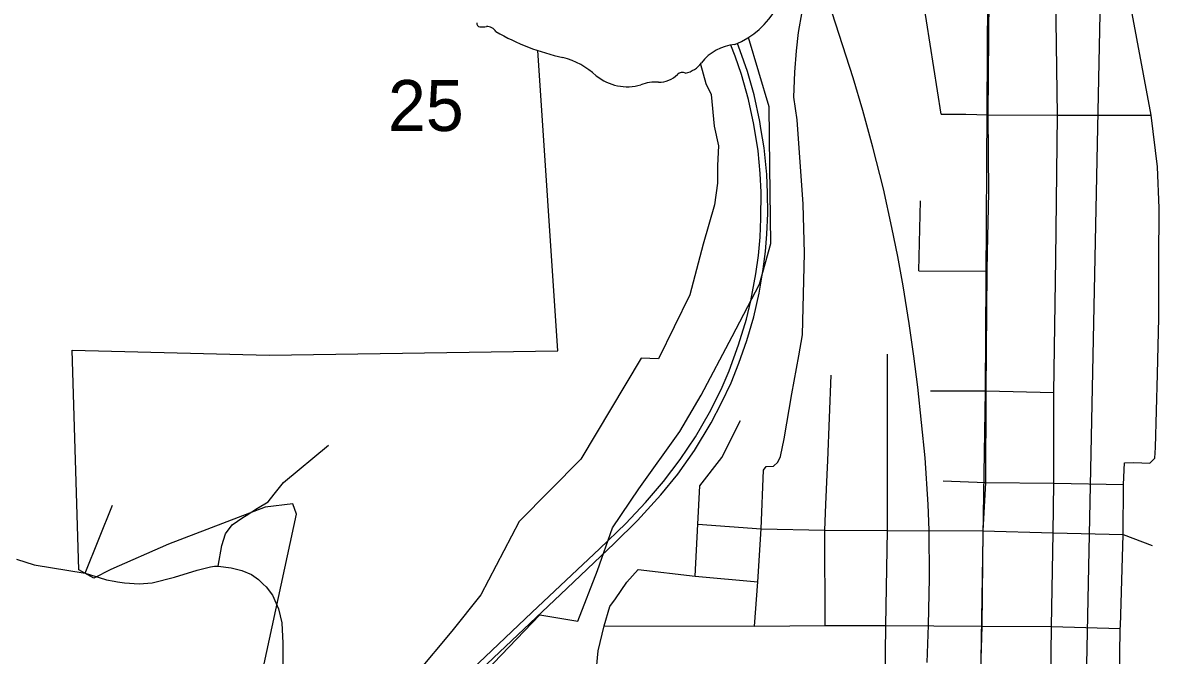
# Model space of a CAD drawing. Extents: x 0 to 34, y 0 to 22.
# Drawn here: x 7.567 to 8.5, y 19.139 to 19.658 of the extents above; entities that cross this region are included whole.
import ezdxf

# ---------------------------------------------------------------- set-up
doc = ezdxf.new("R2010")
doc.units = 0
for name, color, linetype in [('GM_X_City_Street', 7, 'Continuous'), ('GM_X_Corporation', 7, 'Continuous'), ('GM_X_County_Road', 7, 'Continuous'), ('GM_X_Rail_Line', 7, 'Continuous'), ('GM_X_Section', 7, 'Continuous'), ('GM_X_Section_Text', 7, 'Continuous'), ('GM_X_State_Route', 7, 'Continuous'), ('GM_X_State_Shield', 7, 'Continuous')]:
    doc.layers.add(name, color=color, linetype=linetype)

msp = doc.modelspace()

# ---------------------------------------------------------------- linework, layer by layer
at = {"layer": 'GM_X_City_Street'}
for p, q in [((8.32123, 19.58328), (8.30533, 19.68449)), ((8.49377, 19.58232), (8.47461, 19.68388)), ((8.20392, 19.65034), (8.20705, 19.66728)), ((8.20236, 19.63522), (8.20392, 19.65034)), ((8.20106, 19.61775), (8.20236, 19.63522)), ((8.20001, 19.59716), (8.20106, 19.61775)), ((8.20288, 19.57865), (8.20001, 19.59716)), ((8.20783, 19.50931), (8.20288, 19.57865)), ((8.32123, 19.58328), (8.34153, 19.58328)), ((8.34153, 19.58328), (8.35941, 19.5828)), ((8.35941, 19.5828), (8.41668, 19.58232)), ((8.41668, 19.58232), (8.49377, 19.58232)), ((8.49884, 19.54003), (8.49377, 19.58232)), ((8.50029, 19.50596), (8.49884, 19.54003)), ((8.30272, 19.45456), (8.30403, 19.51217)), ((8.20888, 19.46916), (8.20783, 19.50931)), ((8.50005, 19.46198), (8.50029, 19.50596)), ((8.20835, 19.44648), (8.20888, 19.46916)), ((8.4998, 19.41607), (8.50005, 19.46198)), ((8.30272, 19.45456), (8.35869, 19.45425)), ((8.20731, 19.4019), (8.20835, 19.44648)), ((8.49884, 19.36968), (8.4998, 19.41607)), ((8.20418, 19.3847), (8.20731, 19.4019)), ((8.19845, 19.35341), (8.20418, 19.3847)), ((8.27718, 19.26269), (8.27718, 19.386)), ((8.22791, 19.29867), (8.23077, 19.36879)), ((8.49715, 19.3095), (8.49884, 19.36968)), ((8.19219, 19.31666), (8.19845, 19.35341)), ((8.31229, 19.3559), (8.33911, 19.3559)), ((8.33911, 19.3559), (8.34609, 19.3559)), ((8.34609, 19.3559), (8.35772, 19.3559)), ((8.35772, 19.3559), (8.41378, 19.35469)), ((8.14084, 19.30127), (8.15624, 19.33163)), ((8.18906, 19.30206), (8.19219, 19.31666)), ((8.49666, 19.3008), (8.49715, 19.3095)), ((8.12289, 19.27788), (8.14084, 19.30127)), ((8.18333, 19.29424), (8.18698, 19.29736)), ((8.18698, 19.29736), (8.18906, 19.30206)), ((8.22739, 19.2872), (8.22791, 19.29867)), ((8.47177, 19.29694), (8.4795, 19.29718)), ((8.4795, 19.29718), (8.49255, 19.2967)), ((8.49255, 19.2967), (8.49666, 19.3008)), ((8.17316, 19.24262), (8.17523, 19.29086)), ((8.17523, 19.29086), (8.17733, 19.29398)), ((8.17733, 19.29398), (8.18333, 19.29424)), ((8.47092, 19.27913), (8.47177, 19.29694)), ((8.2264, 19.26263), (8.22739, 19.2872)), ((8.3228, 19.28198), (8.35748, 19.28075)), ((8.35748, 19.28075), (8.41378, 19.28003)), ((8.41378, 19.28003), (8.47092, 19.27913)), ((8.47061, 19.23793), (8.47092, 19.27913)), ((8.12126, 19.24647), (8.12289, 19.27788)), ((7.61789, 19.20638), (7.64044, 19.26196)), ((8.22556, 19.24158), (8.2264, 19.26263)), ((8.27718, 19.24132), (8.27718, 19.26269)), ((8.11914, 19.20384), (8.12126, 19.24647)), ((8.12126, 19.24647), (8.17316, 19.24262)), ((8.17055, 19.19908), (8.17316, 19.24262)), ((8.17316, 19.24262), (8.22556, 19.24158)), ((8.22556, 19.24158), (8.27718, 19.24132)), ((8.22582, 19.16337), (8.22556, 19.24158)), ((8.27561, 19.16337), (8.27718, 19.24132)), ((8.27718, 19.24132), (8.35538, 19.24106)), ((8.35538, 19.24106), (8.413, 19.23949)), ((8.413, 19.23949), (8.47061, 19.23793)), ((8.46832, 19.16272), (8.47061, 19.23793)), ((8.47061, 19.23793), (8.49433, 19.22906)), ((8.06289, 19.19882), (8.07228, 19.20925)), ((8.07228, 19.20925), (8.11914, 19.20384)), ((8.11914, 19.20384), (8.17055, 19.19908)), ((8.05351, 19.18527), (8.06289, 19.19882)), ((8.16769, 19.16285), (8.17055, 19.19908)), ((8.04907, 19.17875), (8.05351, 19.18527)), ((8.04438, 19.16311), (8.04907, 19.17875)), ((8.03943, 19.14251), (8.04438, 19.16311)), ((8.04438, 19.16311), (8.16769, 19.16285)), ((8.16769, 19.16285), (8.22582, 19.16337)), ((8.22582, 19.16337), (8.27561, 19.16337)), ((8.27513, 19.10024), (8.27561, 19.16337)), ((8.27561, 19.16337), (8.3546, 19.16285)), ((8.3546, 19.16285), (8.41169, 19.16233)), ((8.41169, 19.16233), (8.46826, 19.16076)), ((8.46748, 19.10967), (8.46826, 19.16076)), ((8.46826, 19.16076), (8.46832, 19.16272)), ((8.03812, 19.12792), (8.03943, 19.14251))]:
    msp.add_line(p, q, dxfattribs=at)
at = {"layer": 'GM_X_Corporation'}
for p, q in [((8.17973, 19.58928), (8.16281, 19.64611)), ((8.00622, 19.38873), (7.98974, 19.63551)), ((8.12332, 19.62431), (8.12779, 19.60835)), ((8.12779, 19.60835), (8.13227, 19.59941)), ((8.13227, 19.59941), (8.13477, 19.57335)), ((8.18042, 19.54022), (8.17973, 19.58928)), ((8.13477, 19.57335), (8.13818, 19.55712)), ((8.13818, 19.55712), (8.13737, 19.54107)), ((8.13737, 19.54107), (8.13736, 19.52664)), ((8.18121, 19.47708), (8.18042, 19.54022)), ((8.13736, 19.52664), (8.13503, 19.50885)), ((8.13503, 19.50885), (8.12573, 19.47639)), ((8.12573, 19.47639), (8.1146, 19.43478)), ((8.17183, 19.44372), (8.18121, 19.47708)), ((8.14956, 19.40074), (8.17183, 19.44372)), ((8.1146, 19.43478), (8.08899, 19.38237)), ((8.12395, 19.35231), (8.14956, 19.40074)), ((7.61267, 19.20906), (7.60727, 19.38935)), ((7.60727, 19.38935), (7.76922, 19.38533)), ((7.76922, 19.38533), (8.00622, 19.38873)), ((8.07464, 19.38285), (8.02502, 19.29976)), ((8.08899, 19.38237), (8.07464, 19.38285)), ((8.10642, 19.3227), (8.12395, 19.35231)), ((8.07274, 19.27562), (8.10642, 19.3227)), ((8.02502, 19.29976), (7.97441, 19.24867)), ((8.05118, 19.24334), (8.07274, 19.27562)), ((7.76576, 19.26035), (7.68632, 19.23008)), ((7.78871, 19.26305), (7.76576, 19.26035)), ((7.7916, 19.25476), (7.78871, 19.26305)), ((7.75651, 19.09318), (7.7916, 19.25476)), ((7.97441, 19.24867), (7.94289, 19.18858)), ((8.03891, 19.20857), (8.05118, 19.24334)), ((7.68632, 19.23008), (7.63909, 19.20926)), ((7.6252, 19.20212), (7.61267, 19.20906)), ((7.63909, 19.20926), (7.6252, 19.20212)), ((8.0228, 19.16687), (8.03891, 19.20857)), ((7.94289, 19.18858), (7.9193, 19.15858)), ((7.94699, 19.12564), (7.99145, 19.17211)), ((7.99145, 19.17211), (8.0228, 19.16687)), ((7.9193, 19.15858), (7.89001, 19.12359))]:
    msp.add_line(p, q, dxfattribs=at)
at = {"layer": 'GM_X_County_Road'}
for p, q in [((8.36027, 19.68458), (8.35941, 19.5828)), ((8.41668, 19.58232), (8.41513, 19.68462)), ((8.35941, 19.5828), (8.35989, 19.51877)), ((8.41523, 19.4644), (8.41668, 19.58232)), ((8.35989, 19.51877), (8.35898, 19.46989)), ((8.35898, 19.46989), (8.35869, 19.45425)), ((8.41378, 19.35469), (8.41523, 19.4644)), ((8.35869, 19.45425), (8.35772, 19.3559)), ((8.35772, 19.3559), (8.35771, 19.35297)), ((8.41378, 19.28003), (8.41378, 19.35469)), ((8.35771, 19.35297), (8.35748, 19.28075)), ((7.78083, 19.28066), (7.81794, 19.31131)), ((7.77337, 19.27109), (7.78083, 19.28066)), ((8.35748, 19.28075), (8.35538, 19.24106)), ((8.413, 19.23949), (8.41378, 19.28003)), ((7.76839, 19.26471), (7.77337, 19.27109)), ((7.75964, 19.25966), (7.76839, 19.26471)), ((7.73864, 19.24585), (7.74758, 19.25208)), ((7.74758, 19.25208), (7.75017, 19.2537)), ((7.75017, 19.2537), (7.75964, 19.25966)), ((7.73319, 19.23847), (7.73864, 19.24585)), ((7.73028, 19.22894), (7.73319, 19.23847)), ((8.35538, 19.24106), (8.3546, 19.16285)), ((8.41169, 19.16233), (8.413, 19.23949)), ((7.72736, 19.21202), (7.73028, 19.22894)), ((7.5615, 19.21785), (7.57609, 19.21299)), ((7.57609, 19.21299), (7.61789, 19.20638)), ((7.61789, 19.20638), (7.63459, 19.20099)), ((7.69149, 19.20308), (7.71006, 19.20872)), ((7.71006, 19.20872), (7.72094, 19.21144)), ((7.72094, 19.21144), (7.72425, 19.21202)), ((7.72425, 19.21202), (7.72736, 19.21202)), ((7.72736, 19.21202), (7.73786, 19.21066)), ((7.73786, 19.21066), (7.74661, 19.20852)), ((7.74661, 19.20852), (7.75458, 19.20502)), ((7.75458, 19.20502), (7.76042, 19.20113)), ((7.63459, 19.20099), (7.63549, 19.20081)), ((7.63549, 19.20081), (7.64181, 19.19958)), ((7.64181, 19.19958), (7.64466, 19.19919)), ((7.64466, 19.19919), (7.65036, 19.19841)), ((7.65036, 19.19841), (7.66242, 19.19744)), ((7.66242, 19.19744), (7.67292, 19.19841)), ((7.67292, 19.19841), (7.69149, 19.20308)), ((7.76042, 19.20113), (7.7643, 19.19724)), ((7.7643, 19.19724), (7.76664, 19.19491)), ((7.76664, 19.19491), (7.77189, 19.1883)), ((7.77189, 19.1883), (7.77694, 19.17702)), ((7.77694, 19.17702), (7.77947, 19.16536)), ((7.77947, 19.16536), (7.78025, 19.14883)), ((8.3546, 19.16285), (8.35277, 19.09939)), ((8.41116, 19.09907), (8.41169, 19.16233)), ((7.78025, 19.14883), (7.78044, 19.12569))]:
    msp.add_line(p, q, dxfattribs=at)
at = {"layer": 'GM_X_Rail_Line'}
for p, q in [((8.35999, 19.82081), (8.35732, 19.35599)), ((8.24884, 19.61311), (8.23153, 19.66654)), ((8.25676, 19.5863), (8.24884, 19.61311)), ((8.26487, 19.55622), (8.25676, 19.5863)), ((8.27368, 19.52198), (8.26487, 19.55622)), ((8.2806, 19.49022), (8.27368, 19.52198)), ((8.28545, 19.46638), (8.2806, 19.49022)), ((8.2898, 19.44214), (8.28545, 19.46638)), ((8.29485, 19.41136), (8.2898, 19.44214)), ((8.29881, 19.38435), (8.29485, 19.41136)), ((8.30207, 19.35892), (8.29881, 19.38435)), ((8.30791, 19.30084), (8.30207, 19.35892)), ((8.35732, 19.35599), (8.34834, 18.78484)), ((8.31038, 19.26265), (8.30791, 19.30084)), ((8.31137, 19.24148), (8.31038, 19.26265)), ((8.31167, 19.2021), (8.31137, 19.24148)), ((8.31068, 19.16341), (8.31167, 19.2021)), ((8.30959, 19.13274), (8.31068, 19.16341))]:
    msp.add_line(p, q, dxfattribs=at)
at = {"layer": 'GM_X_Section'}
msp.add_line((8.46027, 20.09858), (8.43983, 19.09537), dxfattribs=at)
at = {"layer": 'GM_X_State_Route'}
for p, q in [((8.15203, 19.63075), (8.14849, 19.63993)), ((8.15601, 19.63529), (8.15379, 19.64123)), ((8.16211, 19.61814), (8.15601, 19.63529)), ((8.15717, 19.61575), (8.15203, 19.63075)), ((8.16276, 19.59517), (8.15717, 19.61575)), ((8.16759, 19.59906), (8.16211, 19.61814)), ((8.17214, 19.57726), (8.16759, 19.59906)), ((8.1672, 19.57486), (8.16276, 19.59517)), ((8.17311, 19.57135), (8.17214, 19.57726)), ((8.17075, 19.55318), (8.1672, 19.57486)), ((8.17568, 19.55557), (8.17311, 19.57135)), ((8.17241, 19.53444), (8.17075, 19.55318)), ((8.17784, 19.53354), (8.17568, 19.55557)), ((8.17319, 19.51918), (8.17241, 19.53444)), ((8.17853, 19.51867), (8.17784, 19.53354)), ((8.17314, 19.49763), (8.17319, 19.51918)), ((8.17874, 19.50171), (8.17853, 19.51867)), ((8.17246, 19.48213), (8.17314, 19.49763)), ((8.1779, 19.48479), (8.17874, 19.50171)), ((8.17687, 19.47036), (8.1779, 19.48479)), ((8.17103, 19.46721), (8.17246, 19.48213)), ((8.16896, 19.4522), (8.17103, 19.46721)), ((8.17505, 19.45584), (8.17687, 19.47036)), ((8.17158, 19.43617), (8.17505, 19.45584)), ((8.16482, 19.42987), (8.16896, 19.4522)), ((8.16111, 19.41478), (8.16482, 19.42987)), ((8.16737, 19.4168), (8.17158, 19.43617)), ((8.15474, 19.3938), (8.16111, 19.41478)), ((8.16145, 19.39728), (8.16737, 19.4168)), ((8.14691, 19.37239), (8.15474, 19.3938)), ((8.15504, 19.37862), (8.16145, 19.39728)), ((8.14039, 19.3571), (8.14691, 19.37239)), ((8.14873, 19.36262), (8.15504, 19.37862)), ((8.14072, 19.34602), (8.14873, 19.36262)), ((8.13089, 19.3382), (8.14039, 19.3571)), ((8.13217, 19.32962), (8.14072, 19.34602)), ((8.11935, 19.31821), (8.13089, 19.3382)), ((8.11846, 19.30691), (8.13217, 19.32962)), ((8.10677, 19.29952), (8.11935, 19.31821)), ((8.10486, 19.28761), (8.11846, 19.30691)), ((8.09293, 19.28145), (8.10677, 19.29952)), ((8.07816, 19.26423), (8.09293, 19.28145)), ((8.09082, 19.27051), (8.10486, 19.28761)), ((8.07174, 19.24945), (8.09082, 19.27051)), ((8.06224, 19.24705), (8.07816, 19.26423)), ((8.04052, 19.22627), (8.06224, 19.24705)), ((8.05266, 19.23059), (8.07174, 19.24945)), ((8.00836, 19.1887), (8.05266, 19.23059)), ((8.01306, 19.20043), (8.04052, 19.22627)), ((7.98492, 19.17381), (8.01306, 19.20043)), ((7.9432, 19.12716), (8.00836, 19.1887)), ((7.95203, 19.1428), (7.98492, 19.17381)), ((7.92468, 19.11701), (7.95203, 19.1428))]:
    msp.add_line(p, q, dxfattribs=at)
at = {"layer": 'GM_X_State_Shield'}
for centre, radius, start, end in [((8.12512, 19.70502), 0.06994, 292.30889, 8.98584), ((7.94276, 19.65787), 0.00308, 171.95839, 258.30661), ((7.94322, 19.67834), 0.02352, 267.33899, 280.60386), ((7.94804, 19.64676), 0.00848, 29.74838, 93.27175), ((8.0551, 19.82656), 0.20192, 240.41292, 257.1985), ((8.15461, 19.60212), 0.0383, 94.40312, 142.57675), ((7.9949, 19.5684), 0.06318, 47.18416, 75.83597), ((8.10608, 19.63891), 0.0226, 282.87319, 323.27711), ((8.06323, 19.64577), 0.04009, 230.70037, 286.29184), ((8.08932, 19.63078), 0.02136, 268.77702, 315.54927), ((8.10864, 19.6114), 0.00601, 65.75173, 132.64842), ((8.08639, 19.57658), 0.03294, 85.69512, 111.20995)]:
    msp.add_arc(centre, radius, start, end, dxfattribs=at)

# ---------------------------------------------------------------- texts
at = {"layer": 'GM_X_Section_Text'}
msp.add_text('25', height=0.041856, rotation=0.00001, dxfattribs=at).set_placement((7.86671, 19.56939))

doc.saveas('drawing.dxf')
